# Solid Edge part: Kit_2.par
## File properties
Sűrűség: 0,000 kg/m^3
Pontosság: 0,990
Author: ahadarics
Last saved by: psaghy
Revision: 78
Username: ahadarics
Dokumentum tartalom típus: 0
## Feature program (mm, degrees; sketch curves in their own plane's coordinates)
base feature "unnamed BaseFeature 1"
sketch for "Furat_1" plane through (0, 0, -180) normal (0, 0, -1) x-axis (1, 0, 0)
  hole centre (-87.5, 87.5) bore radius 6.9175
hole "Furat_1" nominal diameter 16 finite  ThreadDepth = 24 mm
sketch for "unnamed Hole 1" plane through (0, 0, -180) normal (0, 0, -1) x-axis (1, 0, 0)
  hole centre (-87.5, -87.5) bore radius 6.9175
hole "unnamed Hole 1" finite
sketch for "unnamed Hole 2" plane through (0, 0, -180) normal (0, 0, -1) x-axis (1, 0, 0)
  hole centre (87.5, -87.5) bore radius 6.9175
hole "unnamed Hole 2" finite
sketch for "unnamed Hole 3" plane through (0, 0, -180) normal (0, 0, -1) x-axis (1, 0, 0)
  hole centre (87.5, 87.5) bore radius 6.9175
hole "unnamed Hole 3" finite
pattern "unnamed Pattern 1" of "Furat_1", "unnamed Hole 1", "unnamed Hole 2", "unnamed Hole 3"
sketch for "Furat_5" plane through (15, -109, -154.5) normal (0, -1, 0) x-axis (0, 0, -1)
hole "Furat_5" diameter 26.441 finite  ThreadDepth = 27 mm
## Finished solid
Body 1: solid body, 578 faces, 1370 edges, 836 vertices, 1 internal void.
  Faces by surface: cylinder 188, plane 169, torus 89, spline 52, cone 43, swept 24, sphere 13
  Edges by curve: line 489, curve on surface 452, circle 363, spline 48, intersection 16, ellipse 2
Bounding box of the edges (mm; curved faces can reach further): 220.000 x 220.000 x 58.000, from (-110, -110, -188) to (110, 110, -130).
Cylindrical faces by radius (mm): R0.4595 x1, R0.4687 x2, R0.5232 x1, R0.5393 x1, R0.5479 x1, R0.5619 x1, R0.5738 x1, R0.6109 x1, R0.6383 x1, R0.6502 x1, R0.6941 x1, R0.8155 x1, R0.8225 x2, R0.8412 x1, R0.8677 x1, R0.8728 x1, R0.9072 x1, R0.9543 x1, R0.9562 x1, R1 x20, R1.0015 x4, R1.0018 x2, R1.0187 x1, R1.0708 x1, R1.1067 x1, R1.3671 x1, R1.5 x4, R1.5039 x1, R1.5591 x1, R1.5808 x1, R1.6101 x1, R1.6481 x1, R1.7807 x1, R1.8842 x1, R1.9083 x1, R2 x34, R2.0026 x1, R2.2009 x1, R2.6379 x1, R2.75 x1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
Conical faces (half-angle, radius in mm at the cone's reference point): 0.0011 deg R3.025 x12, 45 deg R3.85 x1, 45 deg R4.25 x1, 45 deg R6.91 x12, 45 deg R8.9 x8, 45 deg R12.055 x1, 45 deg R13.5 x4, 45 deg R20.5 x4
Toroidal faces (ring radius, tube radius in mm): R1.0046 r2.0024 x1, R2 r1 x1, R3.0045 r1.0019 x12, R3.0124 r1.0019 x4, R4 r1 x8, R5.85 r0.2 x1, R6.0859 r3.0037 x6, R6.086 r3.0038 x6, R12 r0.5 x12, R15 r3 x1, R16 r1 x1, R16 r2 x1, R18 r1 x4, R20.5 r1.5 x4, R21 r2 x4, R21 r3 x1, R22 r3 x8, R23.75 r2 x1, R30.5 r2 x1, R33.5 r1 x1, R36.5 r1 x1, R38.5 r1 x1, R39 r1 x1, R42 r2 x8
Spherical faces by radius (mm): R2 x2, R3 x11
Planar faces by outward normal: +x 12, +y 13, +z 11, -x 12, -y 34, -z 53, oblique 34
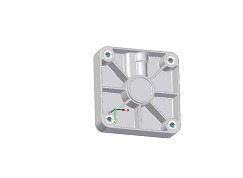
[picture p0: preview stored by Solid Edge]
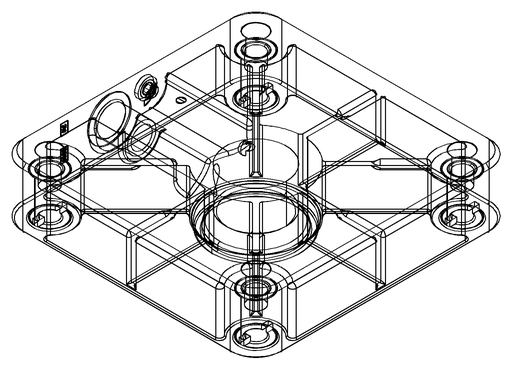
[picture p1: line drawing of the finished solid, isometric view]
